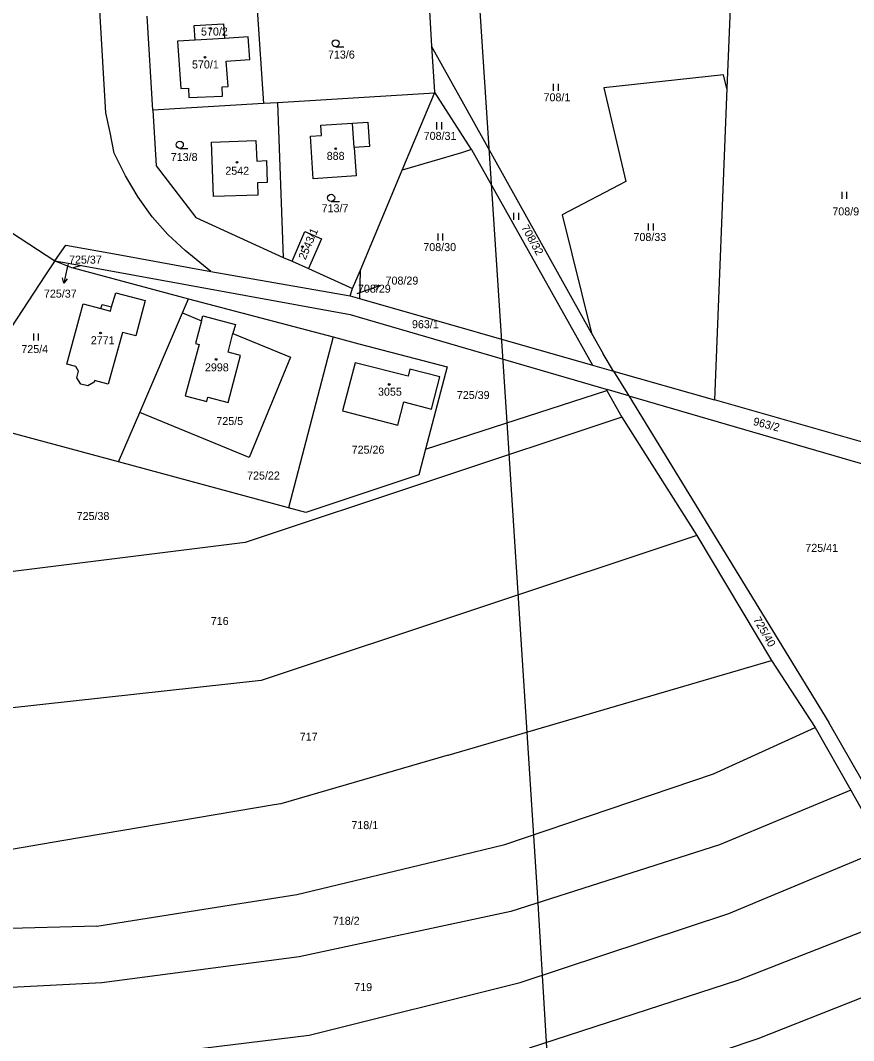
# Model space of a CAD drawing. Extents: x -735249 to -729401, y -1124843 to -1121828.
# Drawn here: x -734125.4 to -733948.5, y -1123919.8 to -1123703.2 of the extents above; entities that cross this region are included whole.
import ezdxf

# ---------------------------------------------------------------- set-up
doc = ezdxf.new("R2010")
doc.units = 0
for name, color, linetype in [('Vrstva 1', 7, 'Continuous'), ('Vrstva 12', 7, 'Continuous'), ('Vrstva 16', 7, 'Continuous'), ('Vrstva 18', 7, 'Continuous'), ('Vrstva 19', 7, 'Continuous'), ('Vrstva 25', 7, 'Continuous'), ('Vrstva 4', 7, 'Continuous')]:
    doc.layers.add(name, color=color, linetype=linetype)

msp = doc.modelspace()

# ---------------------------------------------------------------- linework, layer by layer
at = {"layer": 'Vrstva 1'}
for points in [[(-734107.31, -1123722.82), (-734118.35, -1123534.43)], [(-733974.28, -1123690.36), (-733975.36, -1123717.62)], [(-734038.68, -1123698.72), (-734038.09, -1123708.66)], [(-734075.18, -1123700.89), (-734073.81, -1123720.83)], [(-734097.33, -1123722.23), (-734098.5, -1123702.27)], [(-734088.52, -1123704.28), (-734082.28, -1123703.94)], [(-734082.28, -1123703.94), (-734082.11, -1123707.05)], [(-734088.35, -1123707.39), (-734088.52, -1123704.28)], [(-734082.11, -1123707.05), (-734088.35, -1123707.39)], [(-734004.13, -1123769.58), (-734038.09, -1123708.66)], [(-734038.09, -1123708.66), (-734037.51, -1123718.37)], [(-733976.06, -1123714.74), (-734001.51, -1123717.49)], [(-733975.36, -1123717.62), (-733976.06, -1123714.74)], [(-734037.49, -1123718.67), (-734070.82, -1123720.69)], [(-734044.34, -1123735.01), (-734037.49, -1123718.67)], [(-734029.59, -1123730.64), (-734037.51, -1123718.37)], [(-734037.51, -1123718.37), (-734037.49, -1123718.67)], [(-734001.51, -1123717.49), (-733996.81, -1123737.39)], [(-733975.36, -1123717.62), (-733977.99, -1123783.77)], [(-734073.81, -1123720.83), (-734097.33, -1123722.23)], [(-734070.82, -1123720.69), (-734073.81, -1123720.83)], [(-734070.82, -1123720.69), (-734069.61, -1123753.52)], [(-734106.34, -1123726.99), (-734107.31, -1123722.82)], [(-734097.33, -1123722.23), (-734096.61, -1123734.09)], [(-734061.59, -1123725.46), (-734054.89, -1123725.01)], [(-734061.47, -1123727.61), (-734061.59, -1123725.46)], [(-734054.89, -1123725.01), (-734051.62, -1123724.79)], [(-734051.62, -1123724.79), (-734051.32, -1123729.95)], [(-734105.49, -1123731.37), (-734106.34, -1123726.99)], [(-734063.81, -1123727.74), (-734061.47, -1123727.61)], [(-734063.28, -1123736.87), (-734063.81, -1123727.74)], [(-734084.86, -1123729.02), (-734075.41, -1123728.67)], [(-734084.43, -1123740.62), (-734084.86, -1123729.02)], [(-734075.41, -1123728.67), (-734075.25, -1123733.05)], [(-734051.32, -1123729.95), (-734054.55, -1123730.17)], [(-734103.09, -1123736.19), (-734105.49, -1123731.37)], [(-734054.55, -1123730.17), (-734054.14, -1123736.22)], [(-734031.75, -1123731.28), (-734044.34, -1123735.01)], [(-734029.59, -1123730.64), (-734031.75, -1123731.28)], [(-734029.59, -1123730.64), (-734003.9, -1123776.37)], [(-734096.61, -1123734.09), (-734088.15, -1123745.06)], [(-734075.25, -1123733.05), (-734073.16, -1123732.97)], [(-734073.16, -1123732.97), (-734072.99, -1123737.61)], [(-734100.42, -1123740.72), (-734103.09, -1123736.19)], [(-734054.14, -1123736.22), (-734063.28, -1123736.87)], [(-734053.3, -1123756.37), (-734044.34, -1123735.01)], [(-734072.99, -1123737.61), (-734075.08, -1123737.68)], [(-734075.08, -1123737.68), (-734074.98, -1123740.27)], [(-733996.81, -1123737.39), (-734010.36, -1123744.51)], [(-734097.42, -1123744.87), (-734100.42, -1123740.72)], [(-734074.98, -1123740.27), (-734084.43, -1123740.62)], [(-734136.58, -1123742.24), (-734118.11, -1123754.22)], [(-734094.09, -1123748.64), (-734097.42, -1123744.87)], [(-734088.15, -1123745.06), (-734069.61, -1123753.52)], [(-734010.36, -1123744.51), (-734004.13, -1123769.58)], [(-734090.43, -1123752.05), (-734094.09, -1123748.64)], [(-734067.74, -1123754.33), (-734065.01, -1123748.02)], [(-734065.01, -1123748.02), (-734061.49, -1123749.54)], [(-734061.49, -1123749.54), (-734064.22, -1123755.85)], [(-734118.11, -1123754.22), (-734115.8, -1123750.9)], [(-734115.8, -1123750.9), (-734104.68, -1123752.92)], [(-734104.68, -1123752.92), (-734085, -1123756.5)], [(-734086.56, -1123755.23), (-734090.43, -1123752.05)], [(-734069.61, -1123753.52), (-734067.74, -1123754.33)], [(-734118.11, -1123754.22), (-734120.24, -1123757.45)], [(-734118.11, -1123754.22), (-734114.59, -1123755.66)], [(-734118.11, -1123754.22), (-734112.47, -1123755.25)], [(-734114.59, -1123755.66), (-734114.21, -1123755.76)], [(-734112.47, -1123755.25), (-734114.21, -1123755.76)], [(-734114.21, -1123755.76), (-734089.74, -1123762.34)], [(-734112.47, -1123755.25), (-734055.4, -1123765.65)], [(-734085, -1123756.5), (-734086.56, -1123755.23)], [(-734067.74, -1123754.33), (-734064.22, -1123755.85)], [(-734064.22, -1123755.85), (-734054.87, -1123760.12)], [(-734120.24, -1123757.45), (-734130.99, -1123773.81)], [(-734085, -1123756.5), (-734055.4, -1123761.65)], [(-734054.87, -1123760.12), (-734053.3, -1123756.37)], [(-734053.3, -1123756.37), (-734053.39, -1123762.23)], [(-734055.4, -1123761.65), (-734054.87, -1123760.12)], [(-734106.06, -1123764.04), (-734105.18, -1123761.02)], [(-734105.18, -1123761.02), (-734098.9, -1123762.69)], [(-734091.01, -1123765.31), (-734089.74, -1123762.34)], [(-734089.74, -1123762.34), (-734058.99, -1123770.41)], [(-734055.4, -1123761.65), (-734053.39, -1123762.23)], [(-734053.39, -1123762.23), (-734003.9, -1123776.37)], [(-734115.56, -1123776.18), (-734112.09, -1123763.36)], [(-734112.09, -1123763.36), (-734108.34, -1123764.38)], [(-734108.34, -1123764.38), (-734108.1, -1123763.51)], [(-734108.1, -1123763.51), (-734106.06, -1123764.04)], [(-734098.9, -1123762.69), (-734100.94, -1123770.2)], [(-734100.09, -1123786.45), (-734091.01, -1123765.31)], [(-734091.01, -1123765.31), (-734086.95, -1123766.97)], [(-734086.95, -1123766.97), (-734088.25, -1123771.78)], [(-734086.95, -1123766.97), (-734086.66, -1123765.92)], [(-734086.66, -1123765.92), (-734079.76, -1123767.78)], [(-734055.4, -1123765.65), (-734053.45, -1123766.22)], [(-734053.45, -1123766.22), (-734001, -1123781.52)], [(-734079.76, -1123767.78), (-734080.28, -1123769.7)], [(-734103.73, -1123769.44), (-734106.79, -1123780.45)], [(-734100.94, -1123770.2), (-734103.73, -1123769.44)], [(-734081.34, -1123773.64), (-734080.28, -1123769.7)], [(-734080.28, -1123769.7), (-734068.1, -1123774.68)], [(-734058.99, -1123770.41), (-734068.51, -1123806.66)], [(-734058.99, -1123770.41), (-734053.53, -1123771.85)], [(-734004.13, -1123769.58), (-734001.68, -1123773.97)], [(-734087.49, -1123772.04), (-734090.41, -1123782.93)], [(-734088.25, -1123771.78), (-734087.49, -1123772.04)], [(-734053.53, -1123771.85), (-734034.81, -1123776.76)], [(-734078.67, -1123774.36), (-734081.34, -1123773.64)], [(-734081.31, -1123784.33), (-734078.67, -1123774.36)], [(-734068.1, -1123774.68), (-734076.82, -1123795.97)], [(-733999.44, -1123777.64), (-734001.68, -1123773.97)], [(-734113.68, -1123776.69), (-734115.56, -1123776.18)], [(-734113.11, -1123777.7), (-734113.68, -1123776.69)], [(-734113.42, -1123779.06), (-734113.11, -1123777.7)], [(-734054.36, -1123775.87), (-734057, -1123786.12)], [(-734043.1, -1123778.75), (-734054.36, -1123775.87)], [(-734042.71, -1123777.23), (-734043.1, -1123778.75)], [(-734036.38, -1123778.85), (-734042.71, -1123777.23)], [(-734034.81, -1123776.76), (-734039.39, -1123794.21)], [(-734003.9, -1123776.37), (-733999.44, -1123777.64)], [(-733999.44, -1123777.64), (-733977.99, -1123783.77)], [(-733999.44, -1123777.64), (-733996.19, -1123782.92)], [(-734112.63, -1123780.41), (-734113.42, -1123779.06)], [(-734109.69, -1123779.64), (-734109.78, -1123779.99)], [(-734106.79, -1123780.45), (-734109.69, -1123779.64)], [(-734038.15, -1123785.72), (-734036.38, -1123778.85)], [(-734111.12, -1123780.8), (-734112.63, -1123780.41)], [(-734109.78, -1123779.99), (-734111.12, -1123780.8)], [(-734039.39, -1123794.21), (-734000.86, -1123781.77)], [(-734001, -1123781.52), (-734000.86, -1123781.77)], [(-734001, -1123781.52), (-734000.8, -1123781.58)], [(-734000.86, -1123781.77), (-733997.67, -1123787.45)], [(-733996.19, -1123782.92), (-734000.8, -1123781.58)], [(-734090.41, -1123782.93), (-734085.86, -1123784.14)], [(-734085.86, -1123784.14), (-734085.6, -1123783.17)], [(-734085.6, -1123783.17), (-734081.31, -1123784.33)], [(-734045.28, -1123789.14), (-734044.01, -1123784.2)], [(-734044.01, -1123784.2), (-734038.15, -1123785.72)], [(-733996.19, -1123782.92), (-733953.7, -1123852.28)], [(-733996.19, -1123782.92), (-733930.3, -1123802.1)], [(-733929.91, -1123797.5), (-733977.99, -1123783.77)], [(-734104.59, -1123796.95), (-734100.09, -1123786.45)], [(-734076.82, -1123795.97), (-734100.09, -1123786.45)], [(-734057, -1123786.12), (-734045.28, -1123789.14)], [(-734104.59, -1123796.95), (-734135.67, -1123788.59)], [(-733997.67, -1123787.45), (-734077.7, -1123814.05)], [(-733997.67, -1123787.45), (-733981.76, -1123812.57)], [(-734039.39, -1123794.21), (-734040.83, -1123799.68)], [(-734068.51, -1123806.66), (-734104.59, -1123796.95)], [(-734040.83, -1123799.68), (-734064.81, -1123807.65)], [(-734064.81, -1123807.65), (-734068.51, -1123806.66)], [(-734077.7, -1123814.05), (-734146.29, -1123822.62)], [(-733981.76, -1123812.57), (-734074.32, -1123843.32)], [(-733981.76, -1123812.57), (-733965.9, -1123839.14)], [(-734034.56, -1123859.24), (-733965.9, -1123839.14)], [(-733965.9, -1123839.14), (-733956.63, -1123853.3)], [(-734074.32, -1123843.32), (-734168.36, -1123853.71)], [(-733978.19, -1123863.19), (-733956.63, -1123853.3)], [(-733956.63, -1123853.3), (-733949.07, -1123866.64)], [(-733934.44, -1123885.81), (-733953.7, -1123852.28)], [(-734034.56, -1123859.24), (-734070.1, -1123869.52)], [(-734022.51, -1123878.18), (-733978.19, -1123863.19)], [(-733949.07, -1123866.64), (-733976.97, -1123878.23)], [(-733949.07, -1123866.64), (-733942.03, -1123879.07)], [(-734071.55, -1123869.77), (-734116.19, -1123877.33)], [(-734070.1, -1123869.52), (-734071.55, -1123869.77)], [(-734116.19, -1123877.33), (-734153.75, -1123883.78)], [(-734033.69, -1123880.86), (-734022.51, -1123878.18)], [(-733976.97, -1123878.23), (-734021.29, -1123892.43)], [(-733974.93, -1123892.81), (-733942.03, -1123879.07)], [(-734066.75, -1123888.8), (-734033.69, -1123880.86)], [(-734086.47, -1123891.92), (-734070.77, -1123889.44)], [(-734070.77, -1123889.44), (-734066.75, -1123888.8)], [(-734109.19, -1123895.51), (-734086.47, -1123891.92)], [(-734021.29, -1123892.43), (-734066.25, -1123902.02)], [(-733934.74, -1123892.07), (-733972.94, -1123906.96)], [(-734019.27, -1123907.48), (-733974.93, -1123892.81)], [(-734109.19, -1123895.51), (-734151.35, -1123896.67)], [(-734066.25, -1123902.02), (-734108.11, -1123907.53)], [(-734108.11, -1123907.53), (-734149.51, -1123909.64)], [(-734064.12, -1123918.63), (-734019.27, -1123907.48)], [(-733972.94, -1123906.96), (-734017.4, -1123921.41)], [(-733968.75, -1123919.4), (-733935.72, -1123906.33)], [(-734106.4, -1123923.84), (-734064.12, -1123918.63)], [(-734013.77, -1123934.53), (-733968.75, -1123919.4)]]:
    msp.add_lwpolyline(points, dxfattribs=at)
at = {"layer": 'Vrstva 12'}
for points in [[(-734022.19, -1123786.36), (-734028.96, -1123682.82)], [(-734015.56, -1123889.5), (-734022.19, -1123786.36)], [(-734009.9, -1123983.67), (-734015.56, -1123889.5)]]:
    msp.add_lwpolyline(points, dxfattribs=at)
at = {"layer": 'Vrstva 16'}
for points in [[(-734115.31, -1123755.04), (-734115.54, -1123756.04)], [(-734053.93, -1123761.21), (-734051.9, -1123760.49)]]:
    msp.add_lwpolyline(points, dxfattribs=at)
at = {"layer": 'Vrstva 25'}
for points in [[(-734058.47, -1123708.8), (-734056.72, -1123708.8)], [(-734012.197, -1123718.135), (-734012.197, -1123716.635)], [(-734011.163, -1123718.135), (-734011.163, -1123716.635)], [(-734036.967, -1123726.335), (-734036.967, -1123724.835)], [(-734035.933, -1123726.335), (-734035.933, -1123724.835)], [(-734091.59, -1123730.36), (-734089.84, -1123730.36)], [(-733950.917, -1123741.105), (-733950.917, -1123739.605)], [(-733949.883, -1123741.105), (-733949.883, -1123739.605)], [(-734059.43, -1123741.62), (-734057.68, -1123741.62)], [(-734020.627, -1123745.545), (-734020.627, -1123744.045)], [(-734019.593, -1123745.545), (-734019.593, -1123744.045)], [(-733992.027, -1123747.795), (-733992.027, -1123746.295)], [(-733990.993, -1123747.795), (-733990.993, -1123746.295)], [(-734036.717, -1123749.945), (-734036.717, -1123748.445)], [(-734035.683, -1123749.945), (-734035.683, -1123748.445)], [(-734115.54, -1123756.04), (-734116.214, -1123758.963)], [(-734115.503, -1123758.101), (-734116.214, -1123758.963), (-734116.477, -1123757.876)], [(-734051.9, -1123760.49), (-734049.071, -1123759.494)], [(-734050.18, -1123759.355), (-734049.071, -1123759.494), (-734049.848, -1123760.298)], [(-734122.617, -1123771.165), (-734122.617, -1123769.665)], [(-734121.583, -1123771.165), (-734121.583, -1123769.665)]]:
    msp.add_lwpolyline(points, dxfattribs=at)
for centre, radius in [((-734085.07, -1123704.88), 0.175), ((-734058.47, -1123708.05), 0.75), ((-734086.22, -1123711.01), 0.175), ((-734091.59, -1123729.61), 0.75), ((-734058.47, -1123730.43), 0.175), ((-734079.43, -1123733.3), 0.175), ((-734059.43, -1123740.87), 0.75), ((-734065.52, -1123751.24), 0.175), ((-734108.42, -1123769.58), 0.175), ((-734083.86, -1123775.18), 0.175), ((-734047.09, -1123780.49), 0.175)]:
    msp.add_circle(centre, radius, dxfattribs=at)
at = {"layer": 'Vrstva 4'}
for points in [[(-734088.35, -1123707.39), (-734092.04, -1123707.59)], [(-734092.04, -1123707.59), (-734091.34, -1123717.62)], [(-734077.09, -1123706.66), (-734082.11, -1123707.05)], [(-734076.71, -1123711.49), (-734077.09, -1123706.66)], [(-734081.73, -1123711.88), (-734076.71, -1123711.49)], [(-734081.31, -1123717.24), (-734081.73, -1123711.88)], [(-734091.34, -1123717.62), (-734089.76, -1123717.56)], [(-734089.76, -1123717.56), (-734089.68, -1123719.57)], [(-734089.68, -1123719.57), (-734082.5, -1123719.27)], [(-734082.57, -1123717.29), (-734081.31, -1123717.24)], [(-734082.5, -1123719.27), (-734082.57, -1123717.29)], [(-734054.75, -1123727.14), (-734054.89, -1123725.01)], [(-734054.55, -1123730.17), (-734054.75, -1123727.14)], [(-734108.34, -1123764.38), (-734106.32, -1123764.93)], [(-734106.32, -1123764.93), (-734106.06, -1123764.04)]]:
    msp.add_lwpolyline(points, dxfattribs=at)

# ---------------------------------------------------------------- texts
at = {"layer": 'Vrstva 16'}
for s, p in [('708/29', (-734047.87, -1123759.29)), ('725/37', (-734120.437, -1123762.06))]:
    msp.add_text(s, height=1.7, dxfattribs=at).set_placement(p)
at = {"layer": 'Vrstva 18'}
for s, p in [('713/6', (-734060.1, -1123711.3)), ('708/1', (-734014.31, -1123720.37)), ('708/31', (-734039.77, -1123728.57)), ('713/8', (-734093.5, -1123733.05)), ('713/7', (-734061.45, -1123743.93)), ('708/9', (-733952.97, -1123744.6)), ('708/33', (-733995.21, -1123750.03)), ('708/30', (-734039.85, -1123752.18)), ('725/37', (-734115.11, -1123754.84)), ('708/29', (-734053.73, -1123761.01)), ('963/1', (-734042.26, -1123768.55)), ('725/4', (-734125.24, -1123773.83)), ('725/39', (-734032.73, -1123783.59)), ('725/5', (-734083.82, -1123789.11)), ('725/26', (-734055.08, -1123795.19)), ('725/22', (-734077.28, -1123800.68)), ('725/38', (-734113.49, -1123809.28)), ('725/41', (-733958.71, -1123816.04)), ('716', (-734085, -1123831.57)), ('717', (-734066.1, -1123856.13)), ('718/1', (-734055.13, -1123874.92)), ('718/2', (-734059.07, -1123895.23)), ('719', (-734054.52, -1123909.3))]:
    msp.add_text(s, height=1.7, dxfattribs=at).set_placement(p)
for s, rotation, p in [('708/32', 299.10238, (-734019.108, -1123747.167)), ('963/2', 345.20274, (-733969.926, -1123789.068)), ('725/40', 299.70238, (-733969.828, -1123830.394))]:
    msp.add_text(s, height=1.7, rotation=rotation, dxfattribs=at).set_placement(p)
at = {"layer": 'Vrstva 19'}
for s, p in [('570/2', (-734087.07, -1123706.41)), ('570/1', (-734088.99, -1123713.4)), ('888', (-734060.37, -1123732.81)), ('2542', (-734081.91, -1123735.97)), ('2771', (-734110.48, -1123771.95)), ('2998', (-734086.24, -1123777.71)), ('3055', (-734049.48, -1123782.88))]:
    msp.add_text(s, height=1.7, dxfattribs=at).set_placement(p)
msp.add_text('2543/1', height=1.7, rotation=66.80053, dxfattribs=at).set_placement((-734064.895, -1123754.158))

doc.saveas('drawing.dxf')
